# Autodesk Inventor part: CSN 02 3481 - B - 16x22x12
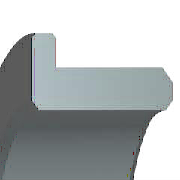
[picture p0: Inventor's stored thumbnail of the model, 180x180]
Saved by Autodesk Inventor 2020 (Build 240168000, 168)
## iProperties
Created: 2019-01
Part Number: CSN 02 3481 - B - 16x22x12
Material: Měď, slitina
Description: Samomazná spékaná pouzdra. Rozměry, typy a tolerance
Document SubType Name: Modeling
Standard: CSN 02 3481
Designer: doma
Standards Organization: CSN
Language: cs-CZ
Size Designation: B - 16x22x12
Categories: <MemberInstance><Categories><Category DisplayName="Součásti hřídele" InternalName="7f7aeb1f-a693-4053-b835-cee3144e0d98" Mnemonic="SHFT"><Category DisplayName="
Density: 8.92 g/cm^3
Appearance: Měď – satén
Mass: 25.2268 g
Surface Area: 22.3729 cm^2
Volume: 2.82811 cm^3
IsCustomPart: 0
Author: doma
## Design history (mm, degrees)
sketch "Náčrt"
  geometry: L1 (0, 0)-(12, 0); L2 (0, 0)-(0, 8); L3 (0, 8)-(12, 8); L4 (12, 8)-(12, 11); L5 (12, 11)-(3, 11); L6 (0, 14)-(0, 8); L7 (0, 14)-(3, 14); L8 (3, 14)-(3, 11); L9 (3, 11)-(3, 11); L10 (3, 11)-(3, 11)
  constraints: 20 end point, 4 parallel, 3 perpendicular, 2 horizontal, 1 vertical
  dimensions: "d0" = 16 diameter of L3 L1 (= WD); "d1" = 22 diameter of L5 L1 (= BD); "d2" = 12 distance of L2.end L3.end (= KB); "d14" = 28 diameter of L7 L1 (= KAD1); "d15" = 0 distance between parallel lines of L5 L9 (computed from STI); "d20" = 3 distance of L6.start L7.end (= SD); "d21" = 0 distance of L8.end L9.end (computed from SBR)
revolve "Těleso" sketch "Náčrt" stored, may be unused: angle "d3" = 90 deg
body "Solid1"
chamfer "Zkosení1" distance "d8" = 0.4001 (computed from WD, KID2); stored, may be unused: second distance "d9" = 0.4001 (computed from PHH4), angle "d32" = 45 deg
chamfer "Zkosení2" distance "d10" = 0.4001 (computed from KAD2, BD); stored, may be unused: second distance "d11" = 0.4001 (computed from PHH1), angle "d33" = 45 deg
chamfer "Zkosení3" distance "d22" = 0.4001 (computed from PHH5); stored, may be unused: second distance "d23" = 0.4001 (computed from PHH2), angle "d34" = 45 deg
chamfer "Zkosení4" distance "d24" = 0.4001 (computed from PHH5); stored, may be unused: second distance "d25" = 0.4001 (computed from PHH5), angle "d35" = 45 deg
chamfer "Zkosení5" distance "d26" = 0.4001 (computed from WD, KID1); stored, may be unused: second distance "d27" = 0.4001 (computed from PHH3), angle "d36" = 45 deg
other parameters: "WD" = 16 [user parameter; used in 4 equation terms], "BD" = 22 [user parameter; used in 3 equation terms], "KB" = 12 [user parameter; used in 1 equation term], "PHH1" = 0.4 [user parameter; used in 5 equation terms], "KID1" = 16.8 [user parameter; used in 2 equation terms], "KAD1" = 28 [user parameter; used in 1 equation term], "PHH2" = 0.4 (= PHH1) [user parameter; used in 1 equation term], "PHH3" = 0.4 (= PHH1) [user parameter; used in 1 equation term], "PHH4" = 0.4 (= PHH1) [user parameter; used in 1 equation term], "KID2" = 16.8 (= KID1) [user parameter; used in 1 equation term], "KAD2" = 21.2 [user parameter; used in 1 equation term], "SD" = 3 [user parameter; used in 1 equation term], "STI" = 0 [user parameter; used in 1 equation term], "SBR" = 0 [user parameter; used in 1 equation term], "PHH5" = 0.4 (= PHH1) [user parameter; used in 3 equation terms], "d28" = 0, "d30" = 0, "d31" = 0, "WR" = 8 (= 0.5 x WD) [user parameter], "BC" = 1000000 [user parameter], "BR" = 11 (= 0.5 x BD) [user parameter], "BBA" = 0 [user parameter], "BC0" = 1000000 [user parameter]
